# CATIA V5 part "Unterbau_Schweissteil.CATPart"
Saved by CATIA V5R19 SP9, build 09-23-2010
Part number: Unterbau_Schweissteil
Bounding box of the stored display mesh (mm): x -100 to 300, y 5 to 200, z 0 to 500
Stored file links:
  D:\Daten\CAD-Daten\Diverse Vorlagen\I-Träger\Unterbau_Schweissteil.CATPart
  D:\Daten\CAD-Daten\Diverse Vorlagen\I-Träger\Unterbau.CATProduct
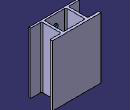
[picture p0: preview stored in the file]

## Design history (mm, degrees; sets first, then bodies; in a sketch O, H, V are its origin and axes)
AxisSystem1: origin (0, 0, 0), X (1, 0, 0), Y (0, 1, 0), Z (0, 0, 1)
Set1
  Plane1: type Offset, RefPlane ZX plane of AxisSystem1, Offset 5
Body1 (main body)
  Body2
    Body3 "Import"
      Solid1: linked copy from another document
    Add1: tool Body3
    Body4
      Body5
        Sketch1 on Plane1, origin (0, 5, 0), H (-1, 0, 0), V (0, 0, 1)
          line L1 (-365.9519, 636.8377) -> (187.9575, 636.8377)
          line L2 (187.9575, 636.8377) -> (187.9575, -156.6484)
          line L3 (187.9575, -156.6484) -> (-365.9519, -156.6484)
          line L4 (-365.9519, -156.6484) -> (-365.9519, 636.8377)
          horizontal: L1 H, L3 H
          vertical: L2 V, L4 V
        Pad1: profile Sketch1, direction (0, -1, 0), length 100
      Add2: tool Body5
      Body6
        Sketch2 on Plane1, origin (225.2167, 5, 85.8149), H (1, 0, 0), V (0, 0, -1)
          point P1 (-129.3479, 2.4656)
          reference projected point E1 (-129.3479, 2.4656) from Sketch3.P2
          coincidence: E1 P1
        Hole1: placed by Sketch2, at (95.8688, 5, 83.3493) direction (0, 1, 0), diameter 50, depth 20
        Sketch3 on Plane1, origin (0, 5, 0), H (-1, 0, 0), V (0, 0, 1)
          point P1 (-99.2568, 406.3433)
          point P2 (-95.8688, 83.3493)
        UserPattern1: of Hole1, copies 2, at the points of Sketch3
      Add3: tool Body6
    Remove1: tool Body4
  Add4: tool Body2
Body7 "Import"
  Body8 "Hauptkörpervon I-Traeger.1"
    Solid2: linked copy from another document
  Add5: tool Body8
  Body9 "Hauptkörpervon I-Traeger.2"
    Solid3: linked copy from another document
  Add6: tool Body9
